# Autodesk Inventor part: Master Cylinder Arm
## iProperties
Shininess: 70.0
Angle Display Precision: 2
Document Length Units: 11269
Document Angle Units: 11279
Document Time Units: 11290
Document Mass Units: 11283
Document Length Units Precision: 3
Document Angle Units Precision: 2
Compacted: True
Created: 2001-08
Part Number: Master Cylinder Arm
Document SubType Name: Modeling
Designer: Martin Budgell
Density: 0.0
Volumn: 0.0
Area: 0.0
PropertySet Name: Model Information
Control State: 0
Master: False
Checked Out: False
Author: Martin Budgell
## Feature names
1. Extrusion1
2. Extrusion2
3. Fillet1
